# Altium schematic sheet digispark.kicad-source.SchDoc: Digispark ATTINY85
size 199 x 139 mm; DrawnBy: Yasir Shahzad; Organization: MASTERMIND Electronics; Revision: 1.0; SheetNumber: 1; SheetTotal: 1
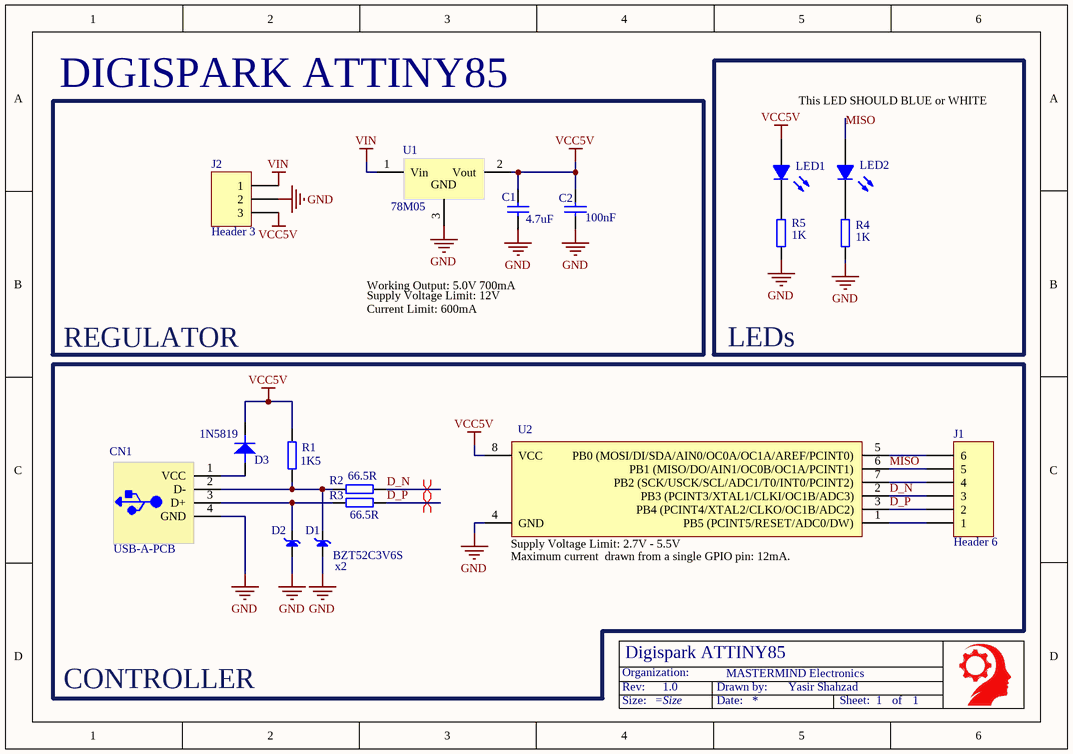
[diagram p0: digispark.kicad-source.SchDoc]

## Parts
*  TitleBlock  (value not drawn)  (graphical)
C1  4.7uF  [C0805]  (value not drawn)
C2  100nF  [C0603]  (value not drawn)
CN1  USB ConnectorsUSBMINIB - Surface Mount Female Mini-B USB Connector 4UConnector: 06564   By microbuilder.euThru-hole RA Female Mini-B USB Connector 4UConnector: 18732   By ladyada.net  [USB-A-PCB]  (value not drawn)  (no BOM)
D1  BZT52C3V6S  [SOD-323]
D2  BZT52C3V6S  [SOD-323]  (value not drawn)
D3  1N5819  [SOD-123HE1_L3.0-W2.0-LS3.7-RD]  (value not drawn)
J1  Header 6  [HDR1X6]
J2  Header 3  [HDR1X3]
LED1  LED Red  [CHIP-LED0603]  (value not drawn)
LED2  LED Green  [CHIP-LED0603]  (value not drawn)
R1  1.5kΩ  [R0603-NO]  (value not drawn)
R2  66.5Ω  [R0603-NO]  (value not drawn)
R3  66.5Ω  [R0603-NO]  (value not drawn)
R4  1kΩ  [R0603-NO]  (value not drawn)
R5  1kΩ  [R0603-NO]  (value not drawn)
U1  78M05  [TO252]
U2  ATTINY85-20SU  [SOIC8_208MIL]  (value not drawn)

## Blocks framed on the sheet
LEDs: LED1 LED2 R4 R5
DIGISPARK ATTINY85: C1 C2 J2 U1

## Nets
GND: C1.2 C2.2 CN1.4(GND) D1.A D2.A J2.2 R4.2 R5.2 U1.3(GND) U2.4(GND)
VCC5V: C1.1 C2.1 D3.1(C) J2.3 LED1.A R1.2 U1.2(Vout) U2.8(VCC)
VIN: J2.1 U1.1(Vin)
D_N: J1.3 R2.2 U2.2(PB3_(PCINT3/XTAL1/CLKI/OC1B/ADC3))
D_P: J1.2 R3.1 U2.3(PB4_(PCINT4/XTAL2/CLKO/OC1B/ADC2))
MISO: J1.5 LED2.A U2.6(PB1_(MISO/DO/AIN1/OC0B/OC1A/PCINT1))
NetCN1_1: CN1.1(VCC) D3.2(A)
NetCN1_2: CN1.2(D-) D1.K(C) R1.1 R2.1
NetCN1_3: CN1.3(D+) D2.K(C) R3.2
NetJ1_1: J1.1 U2.1(PB5_(PCINT5/RESET/ADC0/DW))
NetJ1_4: J1.4 U2.7(PB2_(SCK/USCK/SCL/ADC1/T0/INT0/PCINT2))
NetJ1_6: J1.6 U2.5(PB0_(MOSI/DI/SDA/AIN0/OC0A/OC1A/AREF/PCINT0))
NetLED1_C: LED1.C(K) R5.1
NetLED2_C: LED2.C(K) R4.1

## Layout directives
differential pair: D_N, D_P

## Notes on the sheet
- This LED SHOULD BLUE or WHITE
- (near C1) 4.7uF
- (near C2) 100nF
- (near R5) 1K
- Working Output: 5.0V 700mA
- Supply Voltage Limit: 12V
- (near R4) 1K
- REGULATOR
- Current Limit: 600mA
- (near D3) 1N5819
- (near R1) 1K5
- (near R2) 66.5R
- (near D1) x2
- (near R3) 66.5R
- (near U2) Maximum current  drawn from a single GPIO pin: 12mA.
- (near U2) Supply Voltage Limit: 2.7V - 5.5V
- CONTROLLER

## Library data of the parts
* = TitleBlock: Title Block for Schematic Sheets
C1 = Cap_0805: Capacitor, X5R, ±10%, 6.3V; Manufacturer: N.A.; Specification: X7R, ±10%, 16V
C2 = Cap_0603: Capacitor, X5R, ±10%, 6.3V; Part Number: C0603-N.C.; Manufacturer: N.A.; Artikkelnr Noca: 20069060
CN1 = USB-A-MALE_PCB
D1 D2 = DIODE-BZT52C3V6S: Independent Type 200mW 3.6V~3.8V 3.4V SOD-323 Zener Diodes ROHS; Manufacturer: YFW(佑风微); Symbol: BZT52C3V6S_C5270767; Add into BOM: yes; Reverse Leakage Current (Ir): 5uA@1V; Zener Impedance (Zzt): 90Ω
D3 = DIODE-SOD123: Schottky Diode
J1 = Header 6: Header, 6-Pin
J2 = Header 3: Header, 3-Pin
LED1 LED2 = LEDCHIP-LED0603: SMD lamp beads
R1-R5 = Res_0603: Resistor, ±1%, 0.100W; Part Number: R0603-N.C.Ω; Manufacturer: N.A.; Note: Chip Res
U1 = REG-7805_TO252: 5V Linear Regulator
U2 = ATTINY85-20SU: 8KB 2.7V~5.5V AVR 512Byte 20MHz FLASH 6 SOIC-8-208mil Microcontrollers (MCU/MPU/SOC) ROHS; Manufacturer: MICROCHIP(美国微芯); Add into BOM: yes; GPIO Ports Number: 6; ADC (Bit): 10bit; Peripheral/Function: PWM; Watchdog: 有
